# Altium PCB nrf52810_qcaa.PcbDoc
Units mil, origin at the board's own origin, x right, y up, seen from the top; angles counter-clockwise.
Board outline 1368.03 x 401.03 mil, 2 copper layers (Top Layer, Bottom Layer), stack 65.8 mil thick; 15 components, 29 nets, 63 pads, 66 vias.
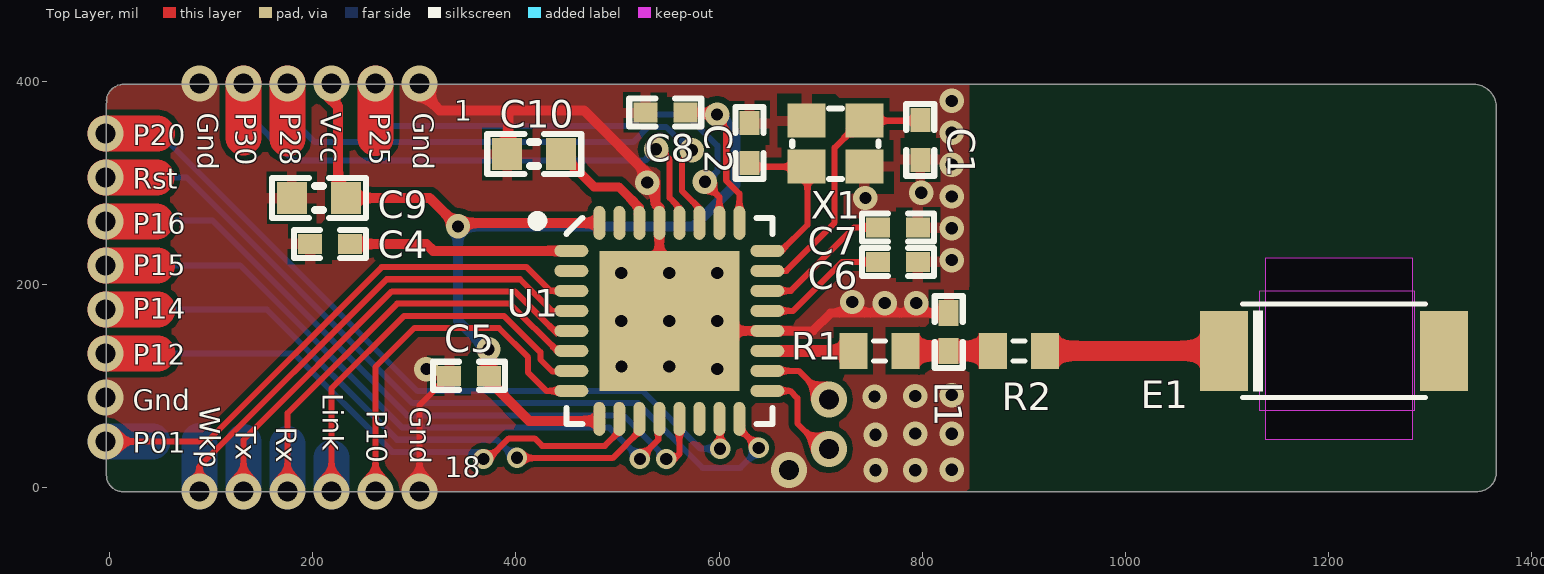
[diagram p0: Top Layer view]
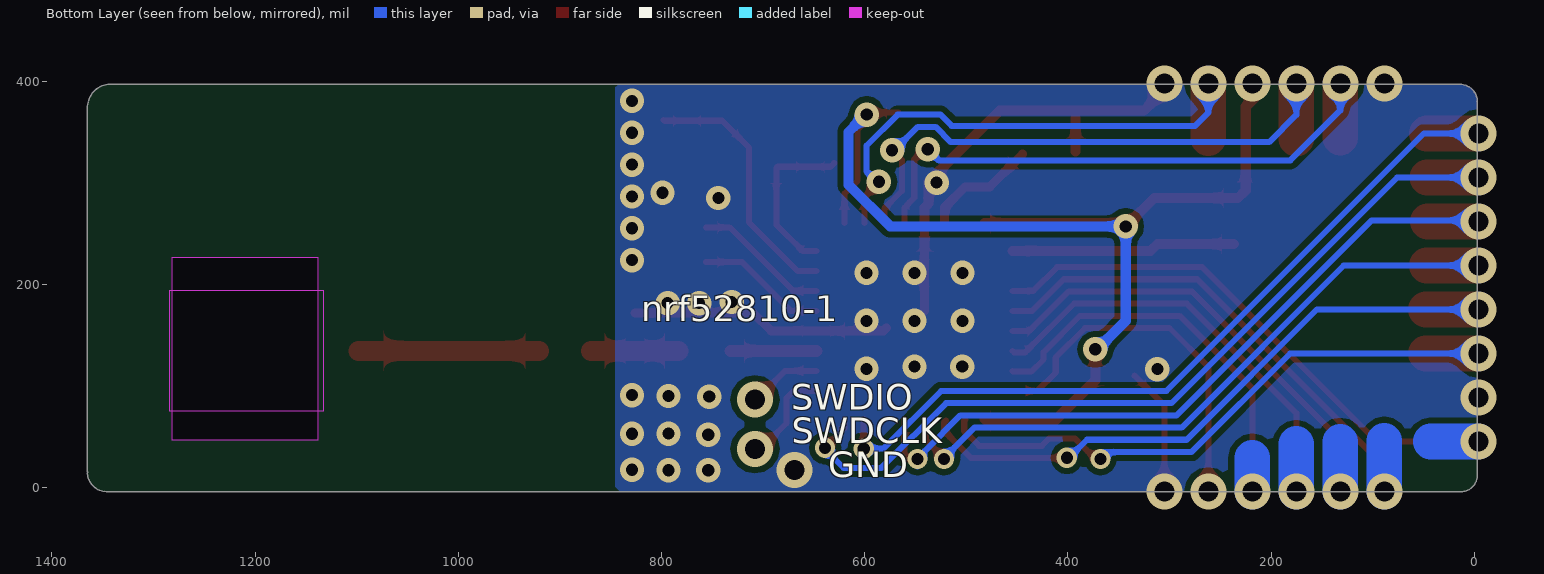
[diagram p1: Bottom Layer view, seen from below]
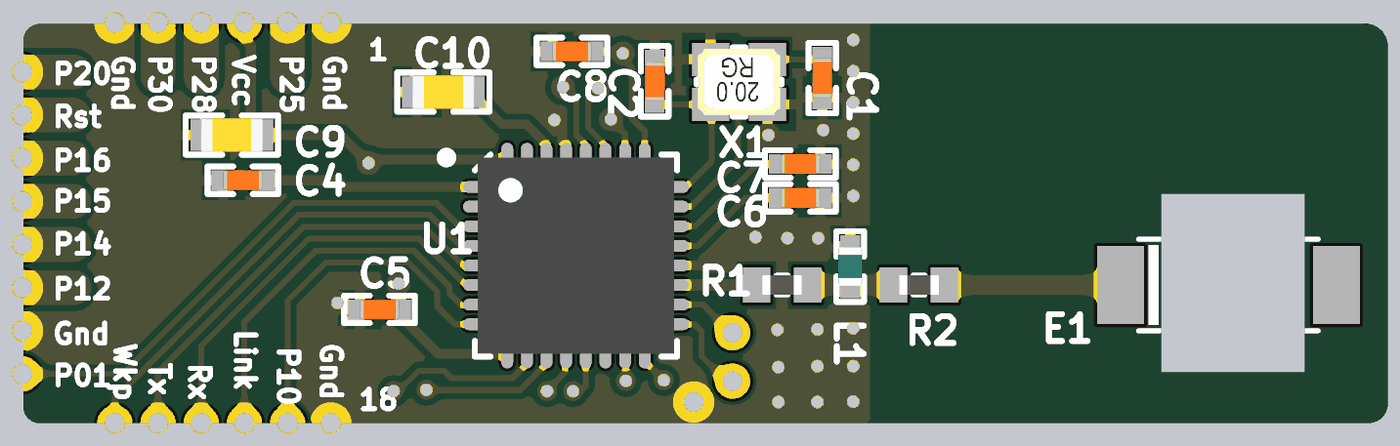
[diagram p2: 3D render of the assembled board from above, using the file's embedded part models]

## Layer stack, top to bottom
Top Solder: solder mask 0.4, Solder Resist, Dk 3.5
Top Layer: signal copper 1.4
Dielectric1: core 63, FR-4, Dk 4.8
Bottom Layer: signal copper 1.4
Bottom Solder: solder mask 0.4, Solder Resist, Dk 3.5

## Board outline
13,-4.02 cw(c13,12) -3.02,12 cw(c0,12) -2.97,12.5 cw(c0,13) -3.02,13 -3.02,378 cw(c0,378) -2.62,379.5 cw(c0,381) -3,381.25 cw(c13.85,379.85) 15.25,396.71 cw(c15,393.7) 15.35,396.7 cw(c15.7,393.7) 15.7,396.72 1339.69,396.72 cw(c1341,394) 1340.85,397.01 cw(c1342,374) 1365.01,375.15 cw(c1362,375) 1365.01,375 cw(c1362,375) 1364.97,374.5 cw(c1362,374) 1365.01,374 1365.01,16 cw(c1362,16) 1364.84,15 cw(c1362,14) 1365.01,14 cw(c1362,14) 1365.01,13.81 cw(c1346,15) 1344.91,-4.02 14,-4.02 cw(c14,-1) 13.5,-3.97 cw(c13,-1)
cut-out: 1138,226 1282,226 1282,47 1138,47

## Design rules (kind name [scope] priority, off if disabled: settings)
Clearance Polygon_ANT [(InNamedPolygon('Top_Layer-GND')) or (InNamedPolygon('Bottom_Layer-GND')) vs InNet('RF')] p1: gap=5 ignorepadtopadclearanceinfootprint=FALSE except(0: Arc-Hole Track-Hole SMDPad-Hole THPad-Hole Via-Hole Fill-Hole Poly-Hole Region-Hole Text-Hole)
Clearance Polygon [(InNamedPolygon('Top_Layer-GND')) or (InNamedPolygon('Bottom_Layer-GND'))] p2: gap=10 ignorepadtopadclearanceinfootprint=FALSE except(0: Arc-Hole Track-Hole SMDPad-Hole THPad-Hole Via-Hole Fill-Hole Poly-Hole Region-Hole Text-Hole)
Clearance [All] p3: gap=6 ignorepadtopadclearanceinfootprint=FALSE except(0: Arc-Hole Track-Hole SMDPad-Hole THPad-Hole Via-Hole Fill-Hole Poly-Hole Region-Hole Text-Hole)
ComponentClearance [All] p1 off: gap=10 collisioncheckmode=3 verticalgap=10 showdistances=FALSE
FabricationTestPointUsage TestPointUsage [All] p1: valid=0 allowmultiple=FALSE
FabricationTestpoint Testpoint [All] p1: side=3 testpointundercomponent=TRUE minsize=40 maxsize=100 preferedsize=60 minholesize=0 maxholesize=40 preferedholesize=32 testpointgrid=1 allowsidetop=TRUE allowsidebottom=TRUE usegrid=TRUE gridtolerance=0.01
Height [All] p1 off: minheight=0 maxheight=1000 prefheight=500
HoleSize [All] p1: absolutevalues=TRUE maxlimit=160 minlimit=12 maxpercent=80.000 minpercent=20.000
MinimumAnnularRing [All] p1 off: minimumring=6
PolygonConnect PolygonConnect_1 [isVia and innet(gnd)] p1: connectstyle=Direct reliefconductorwidth=10 reliefentries=4 polygonreliefangle="90 Angle" airgapwidth=10
PolygonConnect [All] p2: connectstyle=Relief reliefconductorwidth=10 reliefentries=4 polygonreliefangle="90 Angle" airgapwidth=10
RoutingVias [All] p1: holewidth=16 width=32 viastyle="Through Hole" minholewidth=10 minwidth=10 maxholewidth=28 maxwidth=50
SilkToSolderMaskClearance SilkscreenOverComponentPads [IsPad] p1: minsilkscreentomaskgap=10 clearancetoexposedcopper=TRUE
SolderMaskExpansion [All] p1: expansion=3
Width [All] p1: maxlimit=100 minlimit=6 preferedwidth=6
24 further rules are at their usual default settings.

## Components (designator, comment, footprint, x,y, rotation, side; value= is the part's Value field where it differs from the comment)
C1 "12pF" CAPC1005X04L 798,342.22 r270 top
C2 "12pF" CAPC1005X04L 630,339 r90 top
C4 "100nF" CAPC1005X04L 217,239.65 r180 top
C5 "12pF" CAPC1005X04L 354,110 r180 top
C6 "N.C." CAPC1005X04L 776.09,222 r180 top
C7 "100pF" CAPC1005X04L 776.09,256 r0 top
C8 "100nF" CAPC1005X04L 547,369 r180 top
C9 "4.7µF" CAPC1608X06L 206,285 r180 top value=4.7μF
C10 "1.0µF" CAPC1608X06L 418,328.17 r0 top value=1.0μF
E1 "Chip-antenna" C03-CHIP-ANTENNA 1205.27,134.47 r0 top
L1 "15nH" INDC1005X04L 826,153 r270 top
R1 "0" R-0402-1005X40 757.68,134.47 r0 top
R2 "0" R-0402-1005X40 895,134.47 r0 top
U1 "nRF52810-QCAA" Nordic_QFN50P500X500X90-33N 551,164 r0 top locked
X1 "32MHz" BT-XTAL_2016 714.54,338.36 r180 top

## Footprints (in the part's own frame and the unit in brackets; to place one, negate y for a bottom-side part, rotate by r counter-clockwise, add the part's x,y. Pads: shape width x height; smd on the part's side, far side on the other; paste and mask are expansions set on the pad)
BT-XTAL_2016 [mm] "Crystal 2.0 x 1.6 mm"
  rect 0.95x0.85 smd: 1(-0.725,-0.575) 2(0.725,-0.575) 3(0.725,0.575) 4(-0.725,0.575)
  silkscreen extent -1.08,-0.88 1.08,0.88, body extent -1.05,-0.85 1.05,0.85, height 0.56
C03-CHIP-ANTENNA [mm]
  rect 1.2x2 smd: 1(-2.75,0) 2(2.75,0)
  Keep-Out Layer region: 2.007,-1.5 -1.854,-1.5 -1.854,1.5 2.007,1.5
  Keep-Out Layer region: 2.007,-1.5 -1.854,-1.5 -1.854,1.5 2.007,1.5
  silkscreen extent -2.29,-1.17 2.29,1.17
CAPC1005X04L [mm] "Chip Capacitor, 2-Leads, Body 1.0x0.5mm, IPC High Density"
  rect 0.6x0.5 smd: 1(-0.5,0) 2(0.5,0)
  silkscreen extent -0.9,-0.35 0.9,0.35, body extent -0.51,-0.25 0.51,0.25, height 0.5
CAPC1608X06L [mm] "Chip Capacitor, 2-Leads, Body 1.6x0.8mm, IPC High Density"
  rect 0.75x0.8 smd: 1(-0.675,0) 2(0.675,0)
  silkscreen extent -1.17,-0.5 1.17,0.5, body extent -0.8,-0.43 0.8,0.43, height 0.8
INDC1005X04L [mm]
  rect 0.65x0.5 smd: 1(-0.475,0) 2(0.475,0)
  silkscreen extent -0.9,-0.35 0.9,0.35, body extent -0.5,-0.3 0.5,0.3, height 0.5
Nordic_QFN50P500X500X90-33N [mm] "QFN32 5x5x0.85mm, 0.5mm pitch - Medium Density"
  oval 0.85x0.3 smd mask+0.076: 1(-2.45,1.75) 2(-2.45,1.25) 3(-2.45,0.75) 4(-2.45,0.25) 5(-2.45,-0.25) 6(-2.45,-0.75) 7(-2.45,-1.25) 8(-2.45,-1.75) 17(2.45,-1.75) 18(2.45,-1.25) 19(2.45,-0.75) 20(2.45,-0.25) 21(2.45,0.25) 22(2.45,0.75) 23(2.45,1.25) 24(2.45,1.75)
  oval 0.3x0.85 smd mask+0.076: 9(-1.75,-2.45) 10(-1.25,-2.45) 11(-0.75,-2.45) 12(-0.25,-2.45) 13(0.25,-2.45) 14(0.75,-2.45) 15(1.25,-2.45) 16(1.75,-2.45) 25(1.75,2.45) 26(1.25,2.45) 27(0.75,2.45) 28(0.25,2.45) 29(-0.25,2.45) 30(-0.75,2.45) 31(-1.25,2.45) 32(-1.75,2.45)
  rect 3.5x3.5 smd: 33(0,0)
  silkscreen extent -3.42,-2.57 2.57,2.62, body extent -2.5,-2.5 2.5,2.5, height 0.9
R-0402-1005X40 [mm]
  rect 0.7x0.9 smd: 1(-0.65,0) 2(0.65,0)
  silkscreen extent -0.15,-0.25 0.15,0.25, body extent -0.5,-0.25 0.5,0.25, height 0.4

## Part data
C1 C2: library part C0402-12p, "Capacitor, NP0, ±2%"
C4 C8: library part C0402-100n, "Capacitor, X7R, ±10%"
C5: library part CAP_0402, "Capacitor, NP0, ±2%", Part Number=C0402-12p
C6: library part C0402-N.C., "Not mounted"
C7: library part C0402-100p, "Capacitor, NP0, ±5%"
C9: library part C0603-4μ7, "Capacitor, X5R, ±10%"
C10: library part C0603-1μ0, "Capacitor, X7R, ±10%"
E1: "antenna", Package=None
L1: library part IND_0402, "High frequency chip inductor ±10%", Part Number=L0402-15n
R1 R2: library part R-0402, "0402"
U1: "Multi-protocol Bluetooth Low Energy, ANT and 2.4GHz proprietary system-on-chip", Manufacturer="Nordic Semiconductor"
X1: library part XTAL_SMD2016_32MHz_8pF_General, "XTAL SMD 2016, 32MHz, Cl=8pF, Total Tol: ±40ppm"

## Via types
v1: diameter 24, hole 12, Top Layer to Bottom Layer, tented both sides, 28 vias
v2: diameter 35.43, hole 19.68, Top Layer to Bottom Layer, 23 vias
v3: diameter 24, hole 12, Top Layer to Bottom Layer, tented bottom, 9 vias
v4: diameter 20, hole 12, Top Layer to Bottom Layer, tented both sides, 6 vias

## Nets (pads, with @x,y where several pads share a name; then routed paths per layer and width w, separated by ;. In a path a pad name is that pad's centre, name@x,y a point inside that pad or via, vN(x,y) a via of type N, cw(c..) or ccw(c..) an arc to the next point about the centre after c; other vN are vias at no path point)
DEC1: C4.1 U1.1 | length 220.7
  Top Layer w10: C4.1 311.88,239.65 318.63,232.9 U1.1
DEC2: C6.2 U1.21 | length 128.9
  Top Layer w6: U1.21 672.84,173.84 721,222 C6.2
DEC3: C7.1 U1.22 | length 134.8
  Top Layer w6: U1.22 670.53,193.53 733,256 C7.1
DEC4: C10.2 U1.30 | length 113.8
  Top Layer w9: C10.2 476.88,295.86 501.16,295.86 521.47,275.55 U1.30
GND: C1.2 C2.2 C4.2 C5.2 C6.1 C7.2 C8.2 C9.2 C10.1 L1.1 U1.20 U1.29 U1.33 X1.2 X1.4 | length 831.8
  Top Layer w6: v2@305.12,0 305.12,80.8 C5.2 ; 392,371 392.43,370.57
  Top Layer w9: U1.29 541.16,173.84 v3(551,164) ; U1.33@578.56,157.11 581.51,154.16 U1.20 692.16,154.16 709.7,171.7 L1.1
  Top Layer w10: v2@304,392 325,371 392,371 467.16,371 537.28,300.88 537.28,279.39 541.16,275.51 U1.29 ; C10.1@392.43,331 392.43,370.57
  other v1: 754,17 793.09,17.03 829,17.43 753.91,52 793.09,53.03 829,53 753,89.47 793.09,90.03 829,91 311.88,116.51 763,181.53 794,181.53 731,182.62 829,223.81 829,255.14 744,285 829,286.48 799,290.03 529.2,300.1 829,317.82 829,349.15 829,380.49
  other v2: 305.12,-4 669,17.03 -4,88.58 88.58,397.7 305.12,397.7
  other v3: 598.24,116.76 504,119 551,119 503.76,164 598.24,164 503.76,211.24 551,211.24 598.24,211.24
NetL1_2: L1.2 R1.2 R2.1 | length 86.1
  Top Layer w19.68: R1.2 823,134.47 R2.1
NetR1_1: R1.1 U1.19 | length 84.6
  Top Layer w11.81: U1.19 R1.1
P0.01/XL2: U1.3 | length 582.1
  Top Layer w6: v2@0,45.28 96.17,45.28 267.89,217 410.47,217 433.94,193.53 U1.3
  Bottom Layer w35: v2(-4,45.28) 42.72,45.28
P0.04/AIN2: U1.4 | length 525.9
  Top Layer w6: v2@88.58,0 88.58,20.72 272.86,205 404,205 435.16,173.84 U1.4
  Bottom Layer w35: v2(88.58,-4) 88.58,46
P0.05/AIN3: U1.5 | length 495
  Top Layer w6: v2@131.89,0 131.89,46.89 278,193 399,193 437.84,154.16 U1.5
  Bottom Layer w35: v2(131.89,-4) 131.89,44.89
P0.06: U1.6 | length 464.5
  Top Layer w6: v2@175.2,0 175.2,73.2 283,181 394,181 442,133 453.07,133 U1.6
  Bottom Layer w35: v2(175.2,-4) 175.2,42.8
P0.09: U1.7 | length 423.8
  Top Layer w6: v2@218.5,0 218.5,97.5 290,169 388.11,169 424,133.11 424,126 436,114 453.76,114 U1.7
  Bottom Layer w35: v2(218.5,-4) 218.5,29.33
P0.10: U1.8 | length 361.8
  Top Layer w6: v2@261.81,0 261.81,118.81 300,157 383.14,157 412,128.14 412,113.1 430,95.1 U1.8
  other v2: 261.81,-4
P0.12: U1.10 | length 625.9
  Top Layer w6: v4(368,28) 372.8,28 393.13,48.33 418.41,48.33 425.74,41 487.47,41 502,55.53 502,65.76 U1.10@501,66.76
  Top Layer w35: v2(-4,131.89) 47.58,131.89
  Bottom Layer w6: v2@0,131.89 181.29,131.89 278.18,35 361.23,35 368,28.23 v4(368,28)
P0.14: U1.11 | length 656.2
  Top Layer w6: v4(401,29.33) 401.33,29 495.15,29 522,55.85 522,64.07 U1.11@520,66.07
  Top Layer w35: v2(-4,175.2) 47.52,175.2
  Bottom Layer w6: v2@0,175.2 154.95,175.2 283.15,47 381.23,47 398.9,29.33 v4(401,29.33)
P0.15: U1.12 | length 700
  Top Layer w6: v4(522,28) 522,28.87 540.13,47 540.13,66.51 U1.12
  Top Layer w35: v2(-4,218.5) 47,218.5
  Bottom Layer w6: v2@0,218.5 128.61,218.5 288.12,59 492,59 522,29 v4(522,28)
P0.16: U1.13 | length 769.3
  Top Layer w6: v4(548,28) 548,22 549,21 560.84,32.84 U1.13
  Top Layer w35: v2(-4,261.81) 45.81,261.81
  Bottom Layer w6: v2@0,261.81 1.19,263 101.09,263 293.09,71 505.87,71 541,35.87 541,27.87 548,20.87 v4(548,28)
P0.18: U1.14
P0.20: U1.15 | length 810.1
  Top Layer w6: U1.15 601,66.76 v4(601,38.24)
  Top Layer w35: v2(-4,348.43) 47,348.43
  Bottom Layer w6: v2@0,348.43 49.6,348.43 303.03,95 524.84,95 581.6,38.24 v4(601,38.24)
P0.21: U1.16 | length 853.4
  Top Layer w6: U1.16 619.9,58.1 v4(639,39)
  Top Layer w35: v2(-4,305.12) 46.4,305.12
  Bottom Layer w6: v2@0,305.12 75.94,305.12 298.06,83 519.87,83 583.63,19.24 620.89,19.24 639,37.35 v4(639,39)
P0.25: U1.26 | length 526.6
  Top Layer w6: v1(586,301) 586,300.1 600.21,285.89 U1.26
  Top Layer w35: 261.81,343.75 v2(261.81,397.7)
  Bottom Layer w6: v2@261.81,393.7 261.81,368.99 274.8,356 514.33,356 525.33,367 567.7,367 598.24,336.45 598.24,311.24 587,300 v1(586,301)
P0.28/AIN4: U1.27 | length 588.8
  Top Layer w6: v1(573,332) 563.28,322.28 563.28,292.02 580.53,274.77 U1.27
  Top Layer w35: 175.2,343.13 v2(175.2,397.7)
  Bottom Layer w6: v2@175.2,393.7 175.2,366.8 202,340 515.3,340 530.3,355 547.7,355 570.7,332 v1(573,332)
P0.30/AIN6: U1.28 | length 591.4
  Top Layer w6: v1(538,333) 539,333 540,334 551.28,322.72 551.28,285.18 560.84,275.62 U1.28
  Top Layer w35: 131.89,344.46 v2(131.89,397.7)
  Bottom Layer w6: v2@131.89,393.7 131.89,371.11 181,322 527,322 v1(538,333)
RF: E1.1 R2.2 | length 177.4
  Top Layer w19.68: R2.2 E1.1 E1.1@1098,134.47
SWDCLK: U1.17 | length 98.8
  Top Layer w6: U1.17 669.81,95.1 677,87.91 677,63 702,38 v2(708,38)
SWDIO: U1.18 | length 72.2
  Top Layer w6: U1.18 678.21,114.79 706.45,86.54 v2(708,86.54)
VDD_NRF: C5.1 C8.1 C9.1 U1.9 U1.25 U1.32 | length 1183.6
  Top Layer w6: C8.1 591,369 607,353 607,302 619.9,289.1 U1.25
  Top Layer w10: v2@218.5,393.7 218.5,381.53 225,375.03 225,292.57 C9.1 315.03,285 339.57,260.46 U1.32 ; v1(373,136) 373,105.43 412.85,65.57 480.13,65.57 U1.9
  Bottom Layer w10: v1(373,136) 373,134 343,164 v1(343,257) 574.98,257 616,298.02 616,350 599,367 v1(598,367) v1@594.94,367
  other v2: 218.5,397.7
XC1: C1.1 U1.23 X1.1 | length 255.4
  Top Layer w6: U1.23 666.21,213.21 713.7,260.7 713.7,334.5 740.2,361 X1.1 797.09,361 C1.1
XC2: C2.1 U1.24 X1.3 | length 165.2
  Top Layer w6: C2.1 633.59,315.72 X1.3 687,314.72 687,258.65 661.25,232.9 U1.24
pads on no net: E1.2 U1.2 U1.31

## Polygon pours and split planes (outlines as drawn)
GND on Top Layer "Top Layer-No Net" (solid, remove dead copper, pour order 1007): 13,-4.02 cw(c13,12) -3.02,12 cw(c0,12) -2.97,12.5 cw(c0,13) -3.02,13 -3.02,378 cw(c0,378) -2.62,379.5 cw(c0,381) -3,381.25 cw(c13.85,379.85) 15.25,396.71 cw(c15,393.7) 15.35,396.7 cw(c15.7,393.7) 15.7,396.72 847.79,396.72 cw(c850.15,378.85) 868.17,378.85 cw(c850.15,378.85) 868.03,376.6 cw(c865.04,376.97) 868.01,376.5 868.01,271.53 927.53,212.01 1347,212.01 cw(c1347,209) 1347.5,211.97 cw(c1348,209) 1348.1,212.01 cw(c1347.5,194.5) 1365.02,194.5 cw(c1347.5,194.5) 1365.01,193.95 cw(c1347.49,194.5) 1365.01,193.9 1365.01,194 1365.01,76 cw(c1362,76) 1364.97,75.5 cw(c1362,75) 1365,75.31 cw(c1347.5,73.5) 1365.09,73.5 cw(c1347.5,73.5) 1349.31,56 cw(c1349,59) 1349,55.98 926.85,55.98 868.83,-2.03 cw(c866,-1) 866.83,-3.9 cw(c865.3,-1.3) 863.99,-4.02 14,-4.02 cw(c14,-1) 13.5,-3.97 cw(c13,-1)
GND on Bottom Layer "Top Layer-No Net1" (solid, remove dead copper, pour order 1008): 13,-4.02 cw(c13,12) -3.02,12 cw(c0,12) -2.97,12.5 cw(c0,13) -3.02,13 -3.02,378 cw(c0,378) -2.62,379.5 cw(c0,381) -3,381.25 cw(c13.85,379.85) 15.25,396.71 cw(c15,393.7) 15.35,396.7 cw(c15.7,393.7) 15.7,396.72 847.79,396.72 cw(c850.15,378.85) 868.17,378.85 cw(c850.15,378.85) 868.03,376.6 cw(c865.04,376.97) 868.01,376.5 868.01,271.53 927.53,212.01 1347,212.01 cw(c1347,209) 1347.5,211.97 cw(c1348,209) 1348.1,212.01 cw(c1347.5,194.5) 1365.02,194.5 cw(c1347.5,194.5) 1365.01,193.95 cw(c1347.49,194.5) 1365.01,193.9 1365.01,194 1365.01,76 cw(c1362,76) 1364.97,75.5 cw(c1362,75) 1365,75.31 cw(c1347.5,73.5) 1365.09,73.5 cw(c1347.5,73.5) 1349.31,56 cw(c1349,59) 1349,55.98 926.85,55.98 868.83,-2.03 cw(c866,-1) 866.83,-3.9 cw(c865.3,-1.3) 863.99,-4.02 14,-4.02 cw(c14,-1) 13.5,-3.97 cw(c13,-1)

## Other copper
Top Layer:
  pour cut-out: 846,396.72 846,-1 1364.42,-1 1364.56,396.72
Bottom Layer:
  pour cut-out: 1362.22,397.14 1362.22,12.97 1364.64,10.55 1350.12,-3.97 845.62,-3.97 845.62,394.13

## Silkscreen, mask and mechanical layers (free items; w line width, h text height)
Top Overlay:
  text "Gnd" at 87,369 h20 r270
  text "P30" at 124,369 h20 r270
  text "P28" at 168,369 h20 r270
  text "Vcc" at 208,369 h20 r270
  text "P25" at 256,369 h20 r270
  text "Gnd" at 299,369 h20 r270
  text "1" at 339.31,361 h20
  text "P20" at 23,337 h20
  text "Rst" at 23,294 h20
  text "P16" at 23,250 h20
  text "P15" at 23,209 h20
  text "P14" at 23,166 h20
  text "P12" at 23,121 h20
  text "Link" at 210,92.99 h20 r270
  text "Wkp" at 89,79.66 h20 r270
  text "Gnd" at 296,79.66 h20 r270
  text "Gnd" at 23,76 h20
  text "P10" at 253,75.89 h20 r270
  text "Tx" at 124,59.67 h20 r270
  text "Rx" at 164,59.67 h20 r270
  text "P01" at 23,34 h20
  text "18" at 330.02,10 h20
Bottom Overlay:
  text "nrf52810-1" at 820,163.83 h25
  text "SWDIO" at 672.06,76.76 h25
  text "SWDCLK" at 672,43.76 h25
  text "GND" at 635.67,9.97 h25
Mechanical 1:
  lines w6: 0,12 ccw(c13,12) 13,-1 ; 0,13 0,378 ; 0,381 cw(c13.85,379.85) 15,393.7 ; 14,-1 1345,-1 ccw(c1346,15) 1362,14 ; 15.7,393.7 1342.3,393.7 ; 1341,394 cw(c1342,374) 1362,375 ; 1362,16 1362,374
